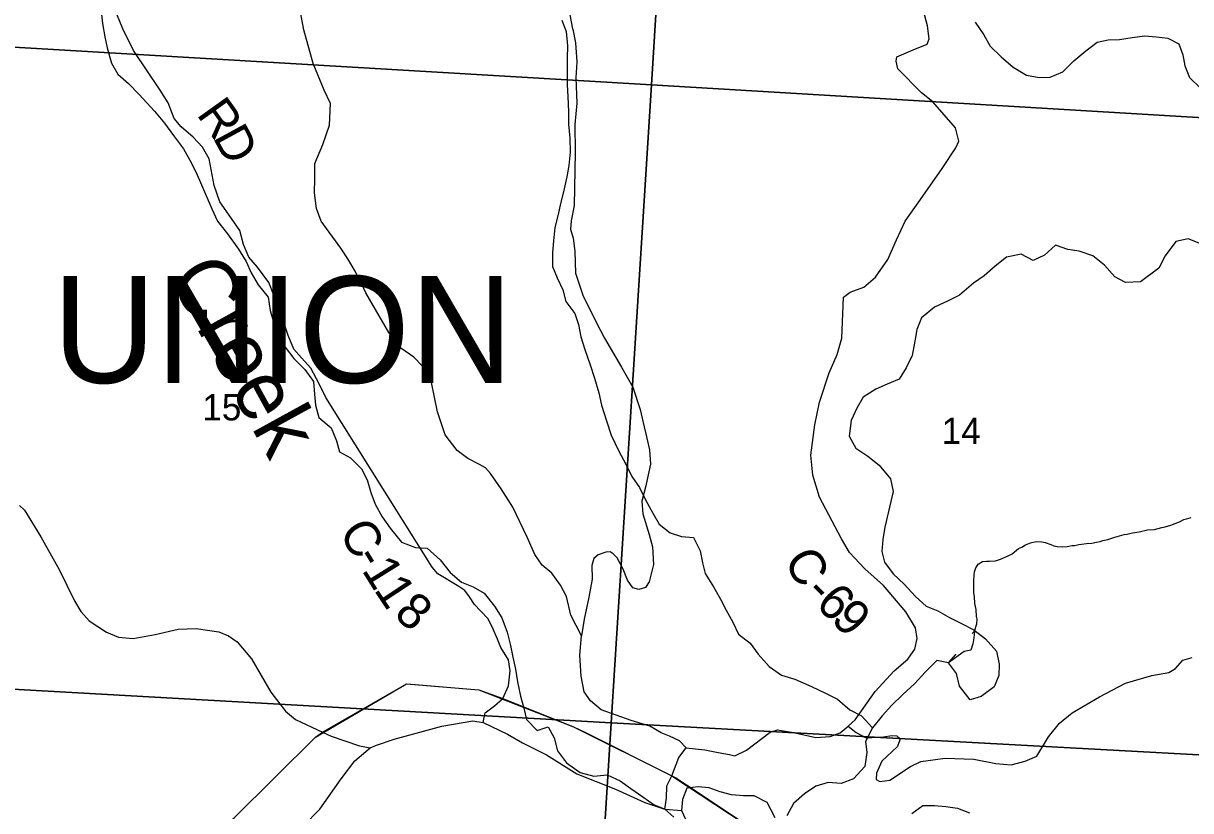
# Model space of a CAD drawing. Extents: x 0 to 34, y 0 to 22.
# Drawn here: x 5.915 to 7.778, y 17.789 to 19.045 of the extents above; entities that cross this region are included whole.
import ezdxf

# ---------------------------------------------------------------- set-up
doc = ezdxf.new("R2010")
doc.units = 0
for name, color, linetype in [('GM_P_State_Alignment', 7, 'Continuous'), ('GM_X_County_Road', 7, 'Continuous'), ('GM_X_County_Road_Text', 7, 'Continuous'), ('GM_X_Minor_River', 7, 'Continuous'), ('GM_X_Minor_River_Text', 7, 'Continuous'), ('GM_X_Section', 7, 'Continuous'), ('GM_X_Section_Text', 7, 'Continuous'), ('GM_X_State_Route', 7, 'Continuous'), ('GM_X_Township_Road', 7, 'Continuous'), ('GM_X_Township_Text', 7, 'Continuous'), ('SH_Data', 7, 'Continuous')]:
    doc.layers.add(name, color=color, linetype=linetype)

msp = doc.modelspace()

# ---------------------------------------------------------------- linework, layer by layer
at = {"layer": 'GM_P_State_Alignment'}
msp.add_lwpolyline([(5.7539, 17.3702), (5.755, 17.3719), (5.7846, 17.4188), (6.0315, 17.5972), (6.2517, 17.7771), (6.3812, 17.906), (6.3923, 17.9142), (6.5211, 17.9881), (6.5265, 17.9911), (6.5405, 17.99), (6.6417, 17.9816), (6.6804, 17.9677), (6.7928, 17.9227), (6.8111, 17.9139), (6.95, 17.8445), (6.9564, 17.8413), (6.9734, 17.8302), (7.1338, 17.7232), (7.4175, 17.6454), (7.7316, 17.5623), (7.9253, 17.5014), (8.1533, 17.4614), (8.4655, 17.4165), (8.5004, 17.4073)], dxfattribs=at)
at = {"layer": 'GM_X_County_Road'}
for points in [[(6.9729, 17.889), (7.0024, 17.886), (7.0237, 17.8815), (7.0419, 17.8785), (7.0506, 17.8762), (7.0692, 17.885), (7.107, 17.914), (7.1184, 17.9178), (7.1441, 17.9137), (7.1798, 17.9054), (7.2025, 17.907), (7.2184, 17.9127), (7.231, 17.9238), (7.2423, 17.9336), (7.2744, 17.9789), (7.3046, 18.012), (7.3262, 18.0306), (7.3375, 18.0466), (7.3412, 18.0637), (7.3386, 18.0804), (7.3233, 18.1058), (7.2876, 18.1478), (7.258, 18.1747), (7.2333, 18.2008), (7.2207, 18.2224), (7.1857, 18.2891), (7.1746, 18.324), (7.1719, 18.3559), (7.1778, 18.4045), (7.1857, 18.4405), (7.2007, 18.4876), (7.2139, 18.5169), (7.2211, 18.5427), (7.2232, 18.5951), (7.224, 18.608), (7.2345, 18.6159), (7.2561, 18.6243), (7.275, 18.6399), (7.2943, 18.6684), (7.3083, 18.6996), (7.3222, 18.7292), (7.3464, 18.7638), (7.3811, 18.8136), (7.4031, 18.8463), (7.4076, 18.8569), (7.4026, 18.8785), (7.3661, 18.9198), (7.3483, 18.9341), (7.3106, 18.9724), (7.308, 18.9845), (7.3091, 18.9917), (7.3348, 19.0028), (7.3572, 19.0119), (7.3606, 19.0203), (7.3579, 19.0412), (7.3399, 19.1094)], [(6.6488, 17.9296), (6.6521, 17.9451), (6.6668, 17.9558), (6.6804, 17.9677), (6.6895, 17.9877), (6.6921, 18.012), (6.6894, 18.0295), (6.6768, 18.0492), (6.6715, 18.0624), (6.6646, 18.0784), (6.6566, 18.095), (6.6448, 18.1075), (6.635, 18.1178), (6.6273, 18.1299), (6.6197, 18.1401), (6.6099, 18.1465), (6.5765, 18.1666), (6.5677, 18.1772), (6.398, 18.4481), (6.3873, 18.4701), (6.374, 18.4951), (6.3588, 18.5114), (6.3466, 18.5254), (6.3379, 18.547), (6.3226, 18.591), (6.307, 18.6316), (6.2887, 18.6558), (6.275, 18.6721), (6.2666, 18.6922), (6.2605, 18.7145), (6.2476, 18.7335), (6.2286, 18.76), (6.2198, 18.7861), (6.2117, 18.829), (6.2011, 18.8476), (6.1862, 18.8635), (6.1669, 18.8801), (6.1559, 18.893), (6.1463, 18.918), (6.1334, 18.9385), (6.0912, 19.0017), (6.074, 19.0362), (6.0595, 19.0715)], [(6.9385, 17.7911), (6.9411, 17.8089), (6.9421, 17.8286), (6.95, 17.8445), (6.9608, 17.8734), (6.9729, 17.889), (6.9622, 17.8999), (6.9459, 17.9075), (6.933, 17.9128), (6.9148, 17.9234), (6.8852, 17.9324), (6.837, 17.9497), (6.8203, 17.9641), (6.81, 17.9785), (6.8051, 18.0032), (6.8031, 18.0366), (6.8056, 18.0677), (6.7889, 18.1007), (6.7816, 18.1307), (6.7725, 18.1488), (6.7584, 18.1678), (6.7428, 18.1803), (6.7314, 18.1977), (6.7188, 18.2254), (6.696, 18.2731), (6.6777, 18.3023), (6.6606, 18.3266), (6.6526, 18.3357), (6.6428, 18.3413), (6.6245, 18.3508), (6.6074, 18.3636), (6.5884, 18.3886), (6.5758, 18.425), (6.5666, 18.4717), (6.5602, 18.4849), (6.5525, 18.4974), (6.5381, 18.5126), (6.5176, 18.5266), (6.4986, 18.552), (6.4617, 18.6152), (6.4449, 18.6497), (6.4331, 18.6691), (6.4217, 18.6861), (6.3905, 18.7293), (6.3829, 18.7494), (6.3798, 18.7748), (6.3805, 18.7968), (6.3804, 18.8215), (6.3932, 18.8518), (6.4038, 18.8826), (6.4052, 18.9171), (6.3953, 18.9384), (6.3774, 18.9808), (6.3629, 19.0347), (6.3571, 19.0654)], [(6.787, 19.0584), (6.7916, 19.0362), (6.7917, 19.0358)], [(6.7917, 19.0358), (6.7962, 19.0141), (6.7985, 18.9837), (6.7967, 18.9583), (6.7983, 18.9177), (6.795, 18.8835), (6.7955, 18.8392), (6.7941, 18.7545), (6.7893, 18.7299), (6.7882, 18.7166), (6.7927, 18.7022), (6.7951, 18.6813), (6.7963, 18.6464), (6.8081, 18.6115), (6.8291, 18.5683), (6.8424, 18.5425), (6.8698, 18.4963), (6.8877, 18.4645), (6.8995, 18.4288), (6.9141, 18.3644), (6.916, 18.3416), (6.9123, 18.3245), (6.9085, 18.3071), (6.9018, 18.2824), (6.9037, 18.2623), (6.9137, 18.2293), (6.919, 18.2099), (6.9206, 18.1818), (6.9135, 18.1537), (6.9078, 18.1446), (6.8972, 18.1419), (6.8877, 18.1442), (6.8793, 18.1563), (6.8721, 18.1741), (6.8626, 18.1923), (6.8565, 18.1988), (6.8516, 18.2018), (6.8447, 18.2014), (6.8322, 18.1968), (6.8254, 18.1911), (6.8224, 18.1801), (6.8225, 18.1581), (6.8172, 18.1296), (6.8098, 18.0943), (6.8056, 18.0677)], [(5.8626, 17.3148), (5.864, 17.3177), (5.8632, 17.3276), (5.8651, 17.3344), (5.8738, 17.3436), (5.9117, 17.3717), (5.9375, 17.3945), (5.9761, 17.4302), (6.0004, 17.4477), (6.0284, 17.4572), (6.0584, 17.4599), (6.1057, 17.4713), (6.1402, 17.4976), (6.1663, 17.5242), (6.1951, 17.5504), (6.2021, 17.56), (6.2341, 17.6043), (6.269, 17.659), (6.2947, 17.6936), (6.3364, 17.7381), (6.3883, 17.7909), (6.4224, 17.8395), (6.444, 17.868), (6.4684, 17.8891)]]:
    msp.add_lwpolyline(points, dxfattribs=at)
at = {"layer": 'GM_X_Minor_River'}
for points in [[(6.0395, 19.0651), (6.0417, 19.0446), (6.0455, 19.0233), (6.0492, 19.0059), (6.056, 18.9816), (6.0658, 18.9641), (6.0832, 18.949), (6.0998, 18.9315), (6.1247, 18.9049), (6.1406, 18.886), (6.155, 18.8662), (6.1708, 18.845), (6.1806, 18.8268), (6.1912, 18.807), (6.1995, 18.7873), (6.2161, 18.7493), (6.2252, 18.7296), (6.241, 18.7091), (6.2584, 18.6848), (6.2705, 18.6651), (6.2788, 18.6469), (6.2901, 18.6279)], [(6.7745, 19.0502), (6.7813, 19.032), (6.7835, 19.0093), (6.7827, 18.9896), (6.7827, 18.9471), (6.7842, 18.9281), (6.7849, 18.9038), (6.7848, 18.8841), (6.7871, 18.8621), (6.7878, 18.8393), (6.7855, 18.8181), (6.7824, 18.7999), (6.7771, 18.7764), (6.7725, 18.7574), (6.7687, 18.74), (6.7634, 18.7195)], [(7.4339, 19.0468), (7.4474, 19.027), (7.458, 19.0088), (7.4754, 18.9914), (7.4943, 18.9754), (7.5155, 18.9625), (7.5359, 18.9587), (7.5533, 18.9594), (7.5738, 18.9678), (7.5912, 18.9852), (7.6102, 19.0011), (7.6283, 19.0148), (7.6458, 19.0186), (7.6639, 19.0193), (7.6844, 19.0223), (7.7041, 19.0253), (7.723, 19.0238), (7.7412, 19.0215), (7.7585, 19.0124), (7.7653, 18.995), (7.7683, 18.9775), (7.7759, 18.9585), (7.7933, 18.9418)], [(6.7634, 18.7195), (6.7611, 18.6982), (6.7595, 18.6793), (6.7595, 18.6573), (6.767, 18.639), (6.7761, 18.6201), (6.7806, 18.6011), (6.7949, 18.5821), (6.801, 18.5647), (6.8047, 18.5449), (6.8108, 18.5245), (6.8198, 18.5002), (6.8266, 18.4789), (6.8334, 18.4554), (6.8379, 18.4357), (6.8454, 18.4106), (6.8529, 18.3879), (6.865, 18.3636), (6.8771, 18.3408), (6.8861, 18.3218), (6.8982, 18.3044), (6.908, 18.2846), (6.9193, 18.2634), (6.9299, 18.2459), (6.9473, 18.2322), (6.9655, 18.2262), (6.9844, 18.2246), (6.995, 18.2034), (6.9987, 18.1844), (7.0032, 18.167), (7.0161, 18.1457), (7.0274, 18.126), (7.0364, 18.1085), (7.047, 18.0895), (7.0561, 18.0705), (7.075, 18.0561), (7.0878, 18.0387), (7.1052, 18.0189), (7.1248, 18.0052), (7.146, 17.9984), (7.1725, 17.987), (7.196, 17.9756), (7.2141, 17.9665), (7.2338, 17.9498), (7.2527, 17.9399), (7.2701, 17.9209)], [(7.7913, 18.6945), (7.7739, 18.7014), (7.7542, 18.6968), (7.7368, 18.6741), (7.7269, 18.6544), (7.6974, 18.6324), (7.6739, 18.6316), (7.6565, 18.6408), (7.6399, 18.659), (7.6217, 18.6742), (7.5998, 18.6818), (7.5816, 18.684), (7.562, 18.6909), (7.5445, 18.675), (7.5263, 18.6666), (7.5074, 18.6765), (7.484, 18.672), (7.4658, 18.6576), (7.4483, 18.6424), (7.4309, 18.6303), (7.4089, 18.6113), (7.3907, 18.6022), (7.3688, 18.5924), (7.3483, 18.575), (7.3407, 18.5568), (7.3376, 18.5378), (7.3331, 18.515), (7.324, 18.4953), (7.3126, 18.4771), (7.2936, 18.4695), (7.2754, 18.4612), (7.255, 18.4483), (7.2451, 18.4309), (7.236, 18.4111), (7.2329, 18.3861), (7.2435, 18.3671), (7.2624, 18.3542), (7.2806, 18.3398), (7.2987, 18.3185)], [(6.2901, 18.6279), (6.306, 18.6082), (6.309, 18.5869), (6.315, 18.5664), (6.321, 18.549), (6.3331, 18.5285), (6.3467, 18.5103), (6.3641, 18.4928), (6.3784, 18.4738), (6.3799, 18.4533), (6.3814, 18.4359), (6.3867, 18.4162), (6.4063, 18.3995), (6.4146, 18.379), (6.4199, 18.3615), (6.4373, 18.3516), (6.4547, 18.3342), (6.4637, 18.3167), (6.4697, 18.2962), (6.4765, 18.278), (6.4878, 18.2575), (6.5007, 18.2393), (6.5188, 18.2173), (6.5408, 18.2089), (6.5597, 18.2074), (6.5801, 18.1892), (6.596, 18.1687), (6.6141, 18.1535), (6.633, 18.1459), (6.6504, 18.136), (6.667, 18.1148), (6.6784, 18.0965), (6.6874, 18.0738), (6.6927, 18.0525), (6.6964, 18.0335), (6.7002, 18.0146), (6.7039, 17.9941), (6.7084, 17.9713), (6.7137, 17.9523), (6.7182, 17.9341), (6.7349, 17.9166), (6.7523, 17.9227), (6.7621, 17.9052), (6.7674, 17.884), (6.7817, 17.865), (6.8036, 17.8498), (6.8256, 17.8437), (6.8468, 17.846), (6.8672, 17.8361), (6.8846, 17.824), (6.9035, 17.811), (6.9217, 17.7981), (6.9391, 17.7913), (6.9655, 17.789)], [(7.2987, 18.3185), (7.3032, 18.2981), (7.2895, 18.2412), (7.2864, 18.2214), (7.2849, 18.2025), (7.2894, 18.185), (7.303, 18.1668), (7.3204, 18.1501), (7.3385, 18.1303), (7.3559, 18.1151), (7.3741, 18.1075), (7.393, 18.0969), (7.4111, 18.0878), (7.4315, 18.0772), (7.4504, 18.0627), (7.4678, 18.043), (7.4723, 18.0225), (7.4715, 18.0043), (7.4639, 17.9861), (7.4435, 17.9709), (7.4261, 17.9656), (7.4087, 17.9876), (7.4042, 18.0074), (7.3913, 18.0248), (7.3724, 18.0286), (7.3542, 18.0097), (7.3375, 17.9915), (7.3186, 17.974), (7.3011, 17.9573), (7.2852, 17.9399), (7.2701, 17.9209), (7.2587, 17.8989), (7.2609, 17.8814), (7.2578, 17.8594), (7.2397, 17.8397), (7.22, 17.8321), (7.1995, 17.8337), (7.1798, 17.8276), (7.1616, 17.8155), (7.1442, 17.8003), (7.1336, 17.7806)], [(7.4289, 18.0713), (7.4327, 18.0754), (7.4367, 18.0867), (7.4368, 18.0943), (7.4361, 18.0985), (7.4352, 18.1099), (7.4335, 18.1194), (7.4329, 18.1304), (7.4319, 18.1365), (7.4317, 18.1491), (7.4315, 18.1552), (7.4324, 18.1643), (7.4329, 18.1699), (7.4349, 18.1764), (7.4384, 18.182), (7.4456, 18.1861), (7.4517, 18.1867), (7.4566, 18.1866), (7.4665, 18.1876), (7.4745, 18.1898), (7.4863, 18.1953), (7.4928, 18.1986), (7.5032, 18.2071), (7.5082, 18.2093), (7.5143, 18.213), (7.5219, 18.2163), (7.5314, 18.218), (7.5401, 18.2175), (7.5454, 18.2167), (7.5548, 18.2135), (7.5593, 18.2115), (7.5646, 18.2103), (7.5729, 18.2097), (7.5805, 18.21), (7.5885, 18.2118), (7.5927, 18.2121), (7.5991, 18.2135), (7.6033, 18.2138), (7.6117, 18.2148), (7.62, 18.2154), (7.6276, 18.2172), (7.6333, 18.2182), (7.6375, 18.22), (7.6455, 18.2214), (7.6569, 18.2254), (7.6714, 18.2293), (7.6763, 18.23), (7.6847, 18.2322), (7.6953, 18.2335), (7.7086, 18.2367), (7.72, 18.2376), (7.7314, 18.2405), (7.7368, 18.2419), (7.7459, 18.2444), (7.7596, 18.2495), (7.7669, 18.2532), (7.7711, 18.2542), (7.7787, 18.2568)], [(7.4327, 18.0754), (7.4317, 18.0644), (7.4301, 18.0549), (7.4267, 18.0447), (7.4161, 18.0428), (7.3913, 18.0248), (7.4029, 18.0378), (7.4029, 18.0382)], [(7.1147, 17.7775), (7.1018, 17.8018), (7.0814, 17.8125), (7.064, 17.8125), (7.0451, 17.814), (7.0269, 17.8186), (7.0095, 17.8254), (6.9921, 17.8269), (6.9739, 17.8247), (6.9671, 17.8065), (6.9655, 17.789), (6.9746, 17.7685)], [(7.3327, 17.7842), (7.3501, 17.7971), (7.369, 17.7971), (7.3872, 17.7956), (7.4054, 17.7926), (7.425, 17.785)]]:
    msp.add_lwpolyline(points, dxfattribs=at)
at = {"layer": 'GM_X_Section'}
for points in [[(5.9068, 20.018), (6.9795, 19.9566), (6.9173, 18.9472), (5.8458, 19.0101)], [(6.9795, 19.9566), (8.0453, 19.8934), (7.9764, 18.8836), (6.9173, 18.9472)], [(6.9173, 18.9472), (6.8533, 17.9287), (5.784, 17.9889), (5.8458, 19.0101)], [(6.9173, 18.9472), (7.9764, 18.8836), (7.9078, 17.8715), (6.8533, 17.9287)], [(5.784, 17.9889), (6.8533, 17.9287), (6.7904, 16.9223), (5.726, 16.9791)], [(6.8533, 17.9287), (7.9078, 17.8715), (7.8396, 16.8632), (6.7904, 16.9223)]]:
    msp.add_lwpolyline(points, close=True, dxfattribs=at)
at = {"layer": 'GM_X_State_Route'}
msp.add_lwpolyline([(5.909, 18.2758), (5.9172, 18.268), (5.9431, 18.2257), (5.9726, 18.1737), (5.9969, 18.1238), (6.0071, 18.1065), (6.0204, 18.0918), (6.048, 18.0733), (6.0668, 18.0656), (6.0906, 18.0635), (6.1253, 18.0696), (6.1623, 18.0786), (6.1911, 18.0794), (6.227, 18.074), (6.2428, 18.0679), (6.2562, 18.0581), (6.2791, 18.031), (6.3101, 17.9779), (6.3333, 17.9477), (6.3493, 17.9344), (6.3923, 17.9142), (6.4063, 17.9077), (6.4518, 17.8922), (6.4684, 17.8891), (6.4788, 17.893), (6.5067, 17.9026), (6.583, 17.9236), (6.6169, 17.9296), (6.6322, 17.9323), (6.6488, 17.9296), (6.6878, 17.9109), (6.7114, 17.897), (6.7497, 17.8776), (6.7981, 17.8477), (6.8602, 17.823), (6.9069, 17.8017), (6.9385, 17.7911), (6.9533, 17.7786)], dxfattribs=at)
at = {"layer": 'GM_X_Township_Road'}
msp.add_lwpolyline([(7.231, 17.9238), (7.2438, 17.9132), (7.2598, 17.9052), (7.2874, 17.9064), (7.3007, 17.9087), (7.309, 17.908), (7.3144, 17.9035), (7.3098, 17.8909), (7.2849, 17.8677), (7.2762, 17.8483), (7.2759, 17.8385), (7.2819, 17.835), (7.2975, 17.8374), (7.3308, 17.8591), (7.347, 17.8671), (7.3857, 17.8725), (7.4319, 17.8711), (7.4668, 17.864), (7.4915, 17.8617), (7.5138, 17.8675), (7.532, 17.8759), (7.5509, 17.9063), (7.5686, 17.9284), (7.5887, 17.9451), (7.6322, 17.9706), (7.6739, 17.9924), (7.7155, 18.0046), (7.7428, 18.0092), (7.7534, 18.0157), (7.7651, 18.029), (7.7799, 18.0332)], dxfattribs=at)
at = {"layer": 'SH_Data'}
msp.add_lwpolyline([(5.7846, 17.4188), (6.0315, 17.5972), (6.2517, 17.7771), (6.3812, 17.906), (6.5265, 17.9911), (6.6417, 17.9816), (6.7928, 17.9227), (6.95, 17.8445), (7.1338, 17.7232), (7.4175, 17.6454), (7.7316, 17.5623), (7.9253, 17.5014)], dxfattribs=at)

# ---------------------------------------------------------------- texts
at = {"layer": 'GM_X_County_Road_Text'}
for s, rotation, p in [('R', 305.5691, (6.1905, 18.8999)), ('D', 298.5165, (6.2167, 18.8635)), ('C', 301.4935, (6.4174, 18.2327)), ('-', 301.5706, (6.4419, 18.1928)), ('C', 298.7994, (7.1278, 18.1889)), ('1', 301.8869, (6.4543, 18.1727)), ('1', 303.5863, (6.4737, 18.1414)), ('-', 313.8988, (7.1599, 18.1349)), ('6', 315.4083, (7.1773, 18.1169)), ('8', 319.3699, (6.5044, 18.0995)), ('9', 314.5368, (7.202, 18.0925))]:
    msp.add_text(s, height=0.0568, rotation=rotation, dxfattribs=at).set_placement(p)
at = {"layer": 'GM_X_Minor_River_Text'}
msp.add_text('Creek', height=0.09468, rotation=298.7949, dxfattribs=at).set_placement((6.146, 18.6416))
at = {"layer": 'GM_X_Section_Text'}
for s, p in [('15', (6.2008, 18.4115)), ('14', (7.3804, 18.3738))]:
    msp.add_text(s, height=0.04186, rotation=0, dxfattribs=at).set_placement(p)
at = {"layer": 'GM_X_Township_Text'}
msp.add_text('UNION', height=0.17045, rotation=0, dxfattribs=at).set_placement((5.9621, 18.4713))

doc.saveas('drawing.dxf')
